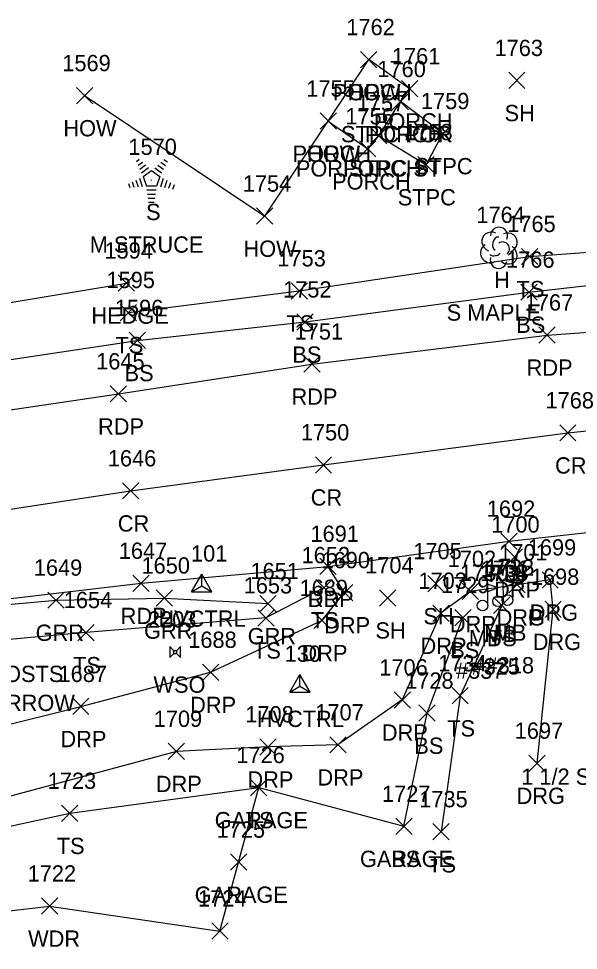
# Model space of a CAD drawing. Extents: x 1761340 to 1763889, y 696770 to 706023.
# Drawn here: x 1761848.8 to 1761917.6, y 700803.7 to 700918.1 of the extents above; entities that cross this region are included whole.
import ezdxf

# ---------------------------------------------------------------- set-up
doc = ezdxf.new("R2010")
doc.units = 0
for name, color, linetype in [('C_A', 7, 'Continuous'), ('C_I', 7, 'Continuous'), ('CPSM', 7, 'Continuous'), ('L_A', 7, 'Continuous'), ('L_C', 7, 'Continuous'), ('L_I', 7, 'Continuous'), ('L_TIC', 7, 'Continuous'), ('LAHR', 7, 'Continuous'), ('LAWA', 7, 'Continuous'), ('LBC', 7, 'Continuous'), ('LBF', 7, 'Continuous'), ('LELB', 7, 'Continuous'), ('LMB', 7, 'Continuous'), ('LTC', 7, 'Continuous'), ('LTD', 7, 'Continuous'), ('P_A', 7, 'Continuous'), ('P_I', 7, 'Continuous'), ('P_TIC', 7, 'Continuous'), ('PET', 7, 'Continuous'), ('PRC', 7, 'Continuous'), ('R_A', 7, 'Continuous'), ('R_C', 7, 'Continuous'), ('R_I', 7, 'Continuous'), ('R_TIC', 7, 'Continuous'), ('RDG', 7, 'Continuous'), ('RDP', 7, 'Continuous'), ('RGR', 7, 'Continuous'), ('S_C', 7, 'Continuous'), ('U_A', 7, 'Continuous'), ('U_I', 7, 'Continuous'), ('UWV', 7, 'Continuous')]:
    doc.layers.add(name, color=color, linetype=linetype)

msp = doc.modelspace()

# ---------------------------------------------------------------- linework, layer by layer
at = {"layer": 'CPSM'}
for p, q in [((1761870.08, 700847.74), (1761871.33, 700849.9)), ((1761872.58, 700847.74), (1761871.33, 700849.9)), ((1761871.33, 700848.46), (1761871.33, 700849.9)), ((1761870.08, 700847.74), (1761871.33, 700848.46)), ((1761871.33, 700848.46), (1761871.33, 700848.46)), ((1761871.33, 700848.46), (1761872.58, 700847.74)), ((1761870.08, 700847.74), (1761872.58, 700847.74)), ((1761882.15, 700835.43), (1761883.4, 700837.59)), ((1761884.65, 700835.43), (1761883.4, 700837.59)), ((1761883.4, 700836.15), (1761883.4, 700837.59)), ((1761882.15, 700835.43), (1761883.4, 700836.15)), ((1761882.15, 700835.43), (1761884.65, 700835.43)), ((1761883.4, 700836.15), (1761883.4, 700836.15)), ((1761883.4, 700836.15), (1761884.65, 700835.43))]:
    msp.add_line(p, q, dxfattribs=at)
at = {"layer": 'L_TIC'}
for points in [[(1761890.84, 700912.08), (1761892.84, 700914.08)], [(1761892.84, 700912.08), (1761890.84, 700914.08)], [(1761890.84, 700912.08), (1761892.84, 700914.08)], [(1761892.84, 700912.08), (1761890.84, 700914.08)], [(1761909.04, 700909.52), (1761911.04, 700911.52)], [(1761911.04, 700909.52), (1761909.04, 700911.52)], [(1761855.95, 700907.66), (1761857.95, 700909.66)], [(1761857.95, 700907.66), (1761855.95, 700909.66)], [(1761895.86, 700908.5), (1761897.86, 700910.5)], [(1761897.86, 700908.5), (1761895.86, 700910.5)], [(1761894.74, 700906.93), (1761896.74, 700908.93)], [(1761896.74, 700906.93), (1761894.74, 700908.93)], [(1761894.74, 700906.93), (1761896.74, 700908.93)], [(1761896.74, 700906.93), (1761894.74, 700908.93)], [(1761885.87, 700904.53), (1761887.87, 700906.53)], [(1761887.87, 700904.53), (1761885.87, 700906.53)], [(1761885.87, 700904.53), (1761887.87, 700906.53)], [(1761887.87, 700904.53), (1761885.87, 700906.53)], [(1761899.96, 700903), (1761901.96, 700905)], [(1761901.96, 700903), (1761899.96, 700905)], [(1761892.07, 700902.73), (1761894.07, 700904.73)], [(1761894.07, 700902.73), (1761892.07, 700904.73)], [(1761892.07, 700902.73), (1761894.07, 700904.73)], [(1761894.07, 700902.73), (1761892.07, 700904.73)], [(1761890.73, 700901.13), (1761892.73, 700903.13)], [(1761892.73, 700901.13), (1761890.73, 700903.13)], [(1761897.89, 700899.18), (1761899.89, 700901.18)], [(1761899.89, 700899.18), (1761897.89, 700901.18)], [(1761878.08, 700892.87), (1761880.08, 700894.87)], [(1761880.08, 700892.87), (1761878.08, 700894.87)], [(1761910.6, 700887.91), (1761912.6, 700889.91)], [(1761912.6, 700887.91), (1761910.6, 700889.91)], [(1761861.08, 700884.65), (1761863.08, 700886.65)], [(1761863.08, 700884.65), (1761861.08, 700886.65)], [(1761882.32, 700883.69), (1761884.32, 700885.69)], [(1761884.32, 700883.69), (1761882.32, 700885.69)], [(1761910.52, 700883.53), (1761912.52, 700885.53)], [(1761912.52, 700883.53), (1761910.52, 700885.53)], [(1761861.33, 700881.03), (1761863.33, 700883.03)], [(1761863.33, 700881.03), (1761861.33, 700883.03)], [(1761883.03, 700879.87), (1761885.03, 700881.87)], [(1761885.03, 700879.87), (1761883.03, 700881.87)], [(1761862.42, 700877.6), (1761864.42, 700879.6)], [(1761864.42, 700877.6), (1761862.42, 700879.6)], [(1761885.34, 700847.25), (1761887.34, 700849.25)], [(1761887.34, 700847.25), (1761885.34, 700849.25)], [(1761899.09, 700847.75), (1761901.09, 700849.75)], [(1761901.09, 700847.75), (1761899.09, 700849.75)], [(1761893.18, 700846), (1761895.18, 700848)], [(1761895.18, 700846), (1761893.18, 700848)], [(1761907.19, 700845.07), (1761909.19, 700847.07)], [(1761909.19, 700845.07), (1761907.19, 700847.07)], [(1761878.23, 700843.54), (1761880.23, 700845.54)], [(1761880.23, 700843.54), (1761878.23, 700845.54)], [(1761902.42, 700843.58), (1761904.42, 700845.58)], [(1761904.42, 700843.58), (1761902.42, 700845.58)], [(1761856.13, 700841.74), (1761858.13, 700843.74)], [(1761858.13, 700841.74), (1761856.13, 700843.74)], [(1761902.08, 700833.98), (1761904.08, 700835.98)], [(1761904.08, 700833.98), (1761902.08, 700835.98)], [(1761898.01, 700831.85), (1761900.01, 700833.85)], [(1761900.01, 700831.85), (1761898.01, 700833.85)], [(1761877.34, 700822.71), (1761879.34, 700824.71)], [(1761879.34, 700822.71), (1761877.34, 700824.71)], [(1761877.34, 700822.71), (1761879.34, 700824.71)], [(1761879.34, 700822.71), (1761877.34, 700824.71)], [(1761854.12, 700819.55), (1761856.12, 700821.55)], [(1761856.12, 700819.55), (1761854.12, 700821.55)], [(1761895.17, 700817.96), (1761897.17, 700819.96)], [(1761897.17, 700817.96), (1761895.17, 700819.96)], [(1761895.17, 700817.96), (1761897.17, 700819.96)], [(1761897.17, 700817.96), (1761895.17, 700819.96)], [(1761899.74, 700817.29), (1761901.74, 700819.29)], [(1761901.74, 700817.29), (1761899.74, 700819.29)], [(1761874.87, 700813.56), (1761876.87, 700815.56)], [(1761876.87, 700813.56), (1761874.87, 700815.56)], [(1761851.65, 700808.17), (1761853.65, 700810.17)], [(1761853.65, 700808.17), (1761851.65, 700810.17)], [(1761872.57, 700805.1), (1761874.57, 700807.1)], [(1761874.57, 700805.1), (1761872.57, 700807.1)], [(1761872.57, 700805.1), (1761874.57, 700807.1)], [(1761874.57, 700805.1), (1761872.57, 700807.1)]]:
    msp.add_lwpolyline(points, dxfattribs=at)
at = {"layer": 'LAHR'}
msp.add_lwpolyline([(1761783.53, 700873.77), (1761811.68, 700880.78), (1761831.53, 700880.58), (1761862.08, 700885.65)], dxfattribs=at)
at = {"layer": 'LAWA'}
msp.add_lwpolyline([(1761809.72, 700797.14), (1761828.97, 700806.42), (1761852.65, 700809.17), (1761873.57, 700806.1)], dxfattribs=at)
at = {"layer": 'LBC'}
for points in [[(1761856.95, 700908.66), (1761879.08, 700893.87), (1761886.87, 700905.53), (1761891.84, 700913.08)], [(1761873.57, 700806.1), (1761875.87, 700814.56), (1761878.34, 700823.71), (1761896.17, 700818.96)]]:
    msp.add_lwpolyline(points, dxfattribs=at)
at = {"layer": 'LBF'}
for points in [[(1761886.87, 700905.53), (1761891.73, 700902.13), (1761893.07, 700903.73), (1761895.74, 700907.93), (1761896.86, 700909.5), (1761891.84, 700913.08)], [(1761893.07, 700903.73), (1761898.89, 700900.18), (1761900.96, 700904), (1761895.74, 700907.93)]]:
    msp.add_lwpolyline(points, dxfattribs=at)
at = {"layer": 'LELB'}
for points in [[(1761723.72, 700872.01), (1761760.57, 700872.12), (1761783.53, 700873.77), (1761799.17, 700869.89), (1761806.34, 700870.91), (1761834.79, 700874.3), (1761863.42, 700878.6), (1761884.03, 700880.87), (1761911.52, 700884.53), (1761932.35, 700886.9), (1761937.16, 700891.64), (1761941.25, 700901.22)], [(1761862.33, 700882.03), (1761883.32, 700884.69), (1761911.6, 700888.91), (1761929.47, 700890.2)], [(1761886.34, 700848.25), (1761879.23, 700844.54), (1761857.13, 700842.74), (1761842.27, 700841.38), (1761813.56, 700834.68), (1761793.54, 700831.19), (1761773.73, 700826.67), (1761754.24, 700823.85), (1761739.4, 700821.55)], [(1761908.19, 700846.07), (1761903.08, 700834.98), (1761900.74, 700818.29)], [(1761896.17, 700818.96), (1761899.01, 700832.85), (1761903.42, 700844.58)], [(1761805.48, 700793.43), (1761803.94, 700799.51), (1761808.7, 700806.69), (1761825.93, 700814.22), (1761855.12, 700820.55), (1761878.34, 700823.71)]]:
    msp.add_lwpolyline(points, dxfattribs=at)
at = {"layer": 'LMB'}
for p, q in [((1761908.38, 700849.18), (1761909.67, 700848.79)), ((1761908.39, 700846.58), (1761908.38, 700849.18)), ((1761909.54, 700849.33), (1761910.83, 700848.95)), ((1761909.54, 700846.74), (1761909.54, 700849.33)), ((1761909.54, 700848.43), (1761910.83, 700848.94)), ((1761906.48, 700848.67), (1761907.77, 700848.29)), ((1761906.49, 700846.08), (1761906.49, 700848.67)), ((1761906.49, 700847.77), (1761907.77, 700848.28)), ((1761908.38, 700848.28), (1761909.67, 700848.79)), ((1761908.89, 700846.73), (1761908.89, 700846.73)), ((1761905.83, 700846.07), (1761905.83, 700846.07)), ((1761907.73, 700846.58), (1761907.73, 700846.58))]:
    msp.add_line(p, q, dxfattribs=at)
for centre in [(1761905.83, 700846.07), (1761907.73, 700846.58), (1761908.89, 700846.73)]:
    msp.add_circle(centre, 0.656, dxfattribs=at)
at = {"layer": 'LTC'}
for p, q in [((1761863.31, 700900.58), (1761863.66, 700900.84)), ((1761863.52, 700900.12), (1761864.05, 700900.5)), ((1761866.33, 700900.48), (1761866.88, 700900.08)), ((1761866.7, 700900.82), (1761867.12, 700900.52)), ((1761863.73, 700899.65), (1761864.43, 700900.16)), ((1761863.94, 700899.19), (1761864.81, 700899.82)), ((1761864.16, 700898.73), (1761865.17, 700899.47)), ((1761865.17, 700899.47), (1761866.17, 700898.74)), ((1761865.59, 700899.78), (1761866.4, 700899.19)), ((1761865.96, 700900.13), (1761866.64, 700899.63)), ((1761863.25, 700898.3), (1761863.52, 700897.46)), ((1761863.71, 700898.51), (1761864.04, 700897.49)), ((1761864.16, 700898.73), (1761864.55, 700897.54)), ((1761866.17, 700898.74), (1761865.78, 700897.54)), ((1761866.61, 700898.47), (1761866.27, 700897.43)), ((1761867.05, 700898.22), (1761866.76, 700897.34)), ((1761862.34, 700897.86), (1761862.49, 700897.39)), ((1761862.79, 700898.08), (1761863.01, 700897.43)), ((1761865.78, 700897.54), (1761864.55, 700897.54)), ((1761865.74, 700897.04), (1761864.59, 700897.04)), ((1761867.5, 700897.97), (1761867.26, 700897.24)), ((1761867.94, 700897.72), (1761867.75, 700897.15)), ((1761865.66, 700896.54), (1761864.67, 700896.54)), ((1761865.57, 700896.04), (1761864.74, 700896.04)), ((1761865.49, 700895.54), (1761864.81, 700895.54))]:
    msp.add_line(p, q, dxfattribs=at)
at = {"layer": 'LTD'}
msp.add_line((1761907.81, 700890.03), (1761907.81, 700890.03), dxfattribs=at)
msp.add_line((1761907.81, 700890.03), (1761907.81, 700890.03), dxfattribs=at)
msp.add_arc((1761907.86, 700891.46), 1.05, 335.5272, 180.9563, dxfattribs=at)
for centre, major_axis, ratio, start_param, end_param in [((1761907.02, 700890.7), (1.21, -0.51), 0.895232, 1.570796, 4.712389), ((1761907.6, 700890.49), (-0.208, -0.792), 0.645439, 3.141593, 6.283185), ((1761908.85, 700890.61), (-1.14, -0.48), 0.949671, 1.570796, 4.712389), ((1761906.73, 700889.32), (0.58, -1.04), 0.959034, 3.141593, 6.283185), ((1761908.31, 700889.86), (-0.5, 0.667), 0.989748, 3.141593, 6.283185), ((1761908.81, 700889.2), (-1.09, 0.79), 0.841452, 1.570796, 4.712389), ((1761907.35, 700889.28), (-0.625, -0.083), 0.423636, 0, 3.141593), ((1761907.81, 700888.53), (0.26, 1.06), 0.942809, 1.570796, 4.712389)]:
    msp.add_ellipse(centre, major_axis=major_axis, ratio=ratio, start_param=start_param, end_param=end_param, dxfattribs=at)
at = {"layer": 'P_TIC'}
for points in [[(1761912.75, 700878.27), (1761914.75, 700880.27)], [(1761914.75, 700878.27), (1761912.75, 700880.27)], [(1761883.87, 700874.71), (1761885.87, 700876.71)], [(1761885.87, 700874.71), (1761883.87, 700876.71)], [(1761860.11, 700871.05), (1761862.11, 700873.05)], [(1761862.11, 700871.05), (1761860.11, 700873.05)], [(1761915.3, 700866.26), (1761917.3, 700868.26)], [(1761917.3, 700866.26), (1761915.3, 700868.26)], [(1761885.29, 700862.33), (1761887.29, 700864.33)], [(1761887.29, 700862.33), (1761885.29, 700864.33)], [(1761861.6, 700859.14), (1761863.6, 700861.14)], [(1761863.6, 700859.14), (1761861.6, 700861.14)], [(1761908.09, 700852.95), (1761910.09, 700854.95)], [(1761910.09, 700852.95), (1761908.09, 700854.95)], [(1761885.86, 700849.87), (1761887.86, 700851.87)], [(1761887.86, 700849.87), (1761885.86, 700851.87)], [(1761862.89, 700847.79), (1761864.89, 700849.79)], [(1761864.89, 700847.79), (1761862.89, 700849.79)]]:
    msp.add_lwpolyline(points, dxfattribs=at)
at = {"layer": 'PET'}
for points in [[(1761729.33, 700852.74), (1761740.9, 700853.18), (1761754.83, 700854.09), (1761780.55, 700856.28), (1761810.22, 700861.14), (1761821.19, 700866.01), (1761839.22, 700868.83), (1761861.11, 700872.05), (1761884.87, 700875.71), (1761913.75, 700879.27), (1761932.44, 700880.62), (1761962.06, 700884.59), (1761979.87, 700885.62), (1762011.62, 700885.45), (1762036.8, 700884.84)], [(1761729.33, 700852.74), (1761727.43, 700840.67), (1761725.47, 700828.38), (1761741.06, 700828.32), (1761766.65, 700830.86), (1761785.9, 700834.25), (1761810.86, 700839.79), (1761840.51, 700846.05), (1761863.89, 700848.79), (1761886.86, 700850.87), (1761909.09, 700853.95), (1761931.55, 700856.46), (1761961.83, 700859.61), (1761986.64, 700861.18), (1762018.61, 700861.2), (1762035.74, 700860.87)]]:
    msp.add_lwpolyline(points, dxfattribs=at)
at = {"layer": 'PRC'}
msp.add_lwpolyline([(1761727.43, 700840.67), (1761741.7, 700841.02), (1761763.59, 700842.8), (1761782.51, 700845.85), (1761809.01, 700850.75), (1761839.73, 700856.65), (1761862.6, 700860.14), (1761886.29, 700863.33), (1761916.3, 700867.26), (1761941.01, 700869.9), (1761962.56, 700871.62), (1761986.3, 700872.71), (1762008.01, 700873.29), (1762036.15, 700873.12)], dxfattribs=at)
at = {"layer": 'R_TIC'}
for points in [[(1761908.75, 700851.01), (1761910.75, 700853.01)], [(1761910.75, 700851.01), (1761908.75, 700853.01)], [(1761885.86, 700849.87), (1761887.86, 700851.87)], [(1761887.86, 700849.87), (1761885.86, 700851.87)], [(1761913.13, 700848.2), (1761915.13, 700850.2)], [(1761915.13, 700848.2), (1761913.13, 700850.2)], [(1761909.06, 700847.6), (1761911.06, 700849.6)], [(1761911.06, 700847.6), (1761909.06, 700849.6)], [(1761909.06, 700847.6), (1761911.06, 700849.6)], [(1761911.06, 700847.6), (1761909.06, 700849.6)], [(1761865.76, 700845.98), (1761867.76, 700847.98)], [(1761867.76, 700845.98), (1761865.76, 700847.98)], [(1761887.88, 700846.64), (1761889.88, 700848.64)], [(1761889.88, 700846.64), (1761887.88, 700848.64)], [(1761903.32, 700846.79), (1761905.32, 700848.79)], [(1761905.32, 700846.79), (1761903.32, 700848.79)], [(1761852.45, 700845.72), (1761854.45, 700847.72)], [(1761854.45, 700845.72), (1761852.45, 700847.72)], [(1761878.49, 700845.3), (1761880.49, 700847.3)], [(1761880.49, 700845.3), (1761878.49, 700847.3)], [(1761899.72, 700844.11), (1761901.72, 700846.11)], [(1761901.72, 700844.11), (1761899.72, 700846.11)], [(1761913.5, 700844.6), (1761915.5, 700846.6)], [(1761915.5, 700844.6), (1761913.5, 700846.6)], [(1761885.1, 700843.23), (1761887.1, 700845.23)], [(1761887.1, 700843.23), (1761885.1, 700845.23)], [(1761871.42, 700836.86), (1761873.42, 700838.86)], [(1761873.42, 700836.86), (1761871.42, 700838.86)], [(1761894.97, 700833.47), (1761896.97, 700835.47)], [(1761896.97, 700833.47), (1761894.97, 700835.47)], [(1761855.49, 700832.67), (1761857.49, 700834.67)], [(1761857.49, 700832.67), (1761855.49, 700834.67)], [(1761878.46, 700827.71), (1761880.46, 700829.71)], [(1761880.46, 700827.71), (1761878.46, 700829.71)], [(1761887.06, 700827.96), (1761889.06, 700829.96)], [(1761889.06, 700827.96), (1761887.06, 700829.96)], [(1761867.22, 700827.16), (1761869.22, 700829.16)], [(1761869.22, 700827.16), (1761867.22, 700829.16)], [(1761911.52, 700825.7), (1761913.52, 700827.7)], [(1761913.52, 700825.7), (1761911.52, 700827.7)]]:
    msp.add_lwpolyline(points, dxfattribs=at)
at = {"layer": 'RDG'}
msp.add_lwpolyline([(1761912.52, 700826.7), (1761914.5, 700845.6), (1761914.13, 700849.2), (1761910.06, 700848.6)], dxfattribs=at)
at = {"layer": 'RDP'}
for points in [[(1761909.75, 700852.01), (1761910.06, 700848.6), (1761904.32, 700847.79), (1761900.72, 700845.11), (1761895.97, 700834.47), (1761888.06, 700828.96), (1761879.46, 700828.71), (1761868.22, 700828.16), (1761843.53, 700821.53), (1761821.66, 700815.81), (1761806.46, 700808.73), (1761801.46, 700801.99), (1761799.74, 700797.31), (1761801.84, 700789.96)], [(1761792.74, 700783.52), (1761789.8, 700796.06), (1761790.69, 700806.51), (1761793.91, 700812.38), (1761809.19, 700820.93), (1761834.4, 700828.2), (1761856.49, 700833.67), (1761872.42, 700837.86), (1761886.1, 700844.23), (1761888.88, 700847.64), (1761886.86, 700850.87)]]:
    msp.add_lwpolyline(points, dxfattribs=at)
at = {"layer": 'RGR'}
msp.add_lwpolyline([(1761841.54, 700845.67), (1761853.45, 700846.72), (1761866.76, 700846.98), (1761879.49, 700846.3)], dxfattribs=at)
at = {"layer": 'UWV'}
for p, q in [((1761867.41, 700841.02), (1761867.96, 700840.47)), ((1761868.74, 700841.02), (1761868.19, 700840.47)), ((1761867.96, 700840.23), (1761867.41, 700839.69)), ((1761868.19, 700840.23), (1761868.74, 700839.69))]:
    msp.add_line(p, q, dxfattribs=at)
for points in [[(1761867.41, 700841.02), (1761867.41, 700839.69)], [(1761868.74, 700839.69), (1761868.74, 700841.02)]]:
    msp.add_lwpolyline(points, dxfattribs=at)
msp.add_lwpolyline([(1761868.31, 700840.35), (1761868.08, 700840.59), (1761867.84, 700840.35), (1761868.08, 700840.12)], close=True, dxfattribs=at)

# ---------------------------------------------------------------- texts
at = {"layer": 'C_A'}
for p in [(1761866.02, 700843.46), (1761878.1, 700831.15)]:
    msp.add_text('HVCTRL', height=2, dxfattribs=at).set_placement(p)
at = {"layer": 'C_I'}
for s, p in [('101', (1761870.02, 700851.46)), ('130', (1761881.52, 700839.15))]:
    msp.add_text(s, height=2, dxfattribs=at).set_placement(p)
at = {"layer": 'L_A'}
for s, p in [('PORCH', (1761887.46, 700908.08)), ('HOW', (1761889.23, 700908.08)), ('SH', (1761908.53, 700905.52)), ('PORCH', (1761892.48, 700904.5)), ('HOW', (1761854.34, 700903.66)), ('STPC POR', (1761888.44, 700902.93)), ('PORCH', (1761891.36, 700902.93)), ('PORCH', (1761882.49, 700900.53)), ('HOW', (1761884.26, 700900.53)), ('POR STPC ST', (1761882.9, 700898.73)), ('PORCH', (1761888.69, 700898.73)), ('STPC', (1761897.47, 700899)), ('PORCH', (1761887.35, 700897.13)), ('STPC', (1761895.41, 700895.18)), ('S', (1761864.5, 700893.38)), ('HOW', (1761876.46, 700888.87)), ('H', (1761907.24, 700885.03)), ('TS', (1761910.01, 700883.91)), ('HEDGE', (1761857.78, 700880.65)), ('TS', (1761881.73, 700879.69)), ('BS', (1761909.96, 700879.53)), ('TS', (1761860.74, 700877.03)), ('BS', (1761882.47, 700875.87)), ('BS', (1761861.86, 700873.6)), ('SH', (1761898.57, 700843.75)), ('TS', (1761884.75, 700843.25)), ('SH', (1761892.67, 700842)), ('MB', (1761906.04, 700841.58)), ('MB', (1761907.2, 700841.73)), ('MB', (1761904.14, 700841.07)), ('TS', (1761906.6, 700841.07)), ('TS', (1761877.64, 700839.54)), ('BS', (1761901.86, 700839.58)), ('TS', (1761855.54, 700837.74)), ('TS', (1761901.49, 700829.98)), ('BS', (1761897.45, 700827.85)), ('GARAGE', (1761872.93, 700818.71)), ('TS', (1761876.75, 700818.71)), ('TS', (1761853.53, 700815.55)), ('GARAGE', (1761890.77, 700813.96)), ('BS', (1761894.61, 700813.96)), ('TS', (1761899.15, 700813.29)), ('GARAGE', (1761870.47, 700809.56)), ('WDR', (1761850.01, 700804.17))]:
    msp.add_text(s, height=2, dxfattribs=at).set_placement(p)
at = {"layer": 'L_C'}
for s, p in [('M STRUCE', (1761857.58, 700889.38)), ('S MAPLE', (1761901.42, 700881.03)), ('#318', (1761906.2, 700837.73)), ('#337', (1761902.57, 700837.07)), ('#325', (1761904.47, 700837.58)), ('1 1/2 STORY WOOD FRAME#325', (1761910.58, 700824.05))]:
    msp.add_text(s, height=2, dxfattribs=at).set_placement(p)
at = {"layer": 'L_I'}
for s, p in [('1762', (1761889.1, 700916.08)), ('1762', (1761889.1, 700916.08)), ('1763', (1761907.3, 700913.52)), ('1761', (1761894.69, 700912.5)), ('1569', (1761854.21, 700911.66)), ('1760', (1761892.91, 700910.93)), ('1760', (1761892.91, 700910.93)), ('1755', (1761884.18, 700908.53)), ('1755', (1761884.18, 700908.53)), ('1757', (1761890.38, 700906.73)), ('1757', (1761890.38, 700906.73)), ('1759', (1761898.26, 700907)), ('1756', (1761888.98, 700905.13)), ('1758', (1761896.2, 700903.18)), ('1570', (1761862.33, 700901.38)), ('1754', (1761876.38, 700896.87)), ('1764', (1761905.07, 700893.03)), ('1765', (1761908.86, 700891.91)), ('1594', (1761859.39, 700888.65)), ('1753', (1761880.63, 700887.69)), ('1766', (1761908.72, 700887.53)), ('1595', (1761859.64, 700885.03)), ('1752', (1761881.33, 700883.87)), ('1596', (1761860.67, 700881.6)), ('1705', (1761897.32, 700851.75)), ('1652', (1761883.6, 700851.25)), ('1704', (1761891.41, 700850)), ('1731', (1761905.6, 700849.58)), ('1732', (1761906.2, 700849.73)), ('1730', (1761903.05, 700849.07)), ('1733', (1761905.5, 700849.07)), ('1653', (1761876.49, 700847.54)), ('1729', (1761900.72, 700847.58)), ('1654', (1761854.39, 700845.74)), ('1734', (1761900.38, 700837.98)), ('1728', (1761896.32, 700835.85)), ('1726', (1761875.59, 700826.71)), ('1726', (1761875.59, 700826.71)), ('1723', (1761852.42, 700823.55)), ('1727', (1761893.48, 700821.96)), ('1727', (1761893.48, 700821.96)), ('1735', (1761898.05, 700821.29)), ('1725', (1761873.17, 700817.56)), ('1722', (1761849.95, 700812.17)), ('1724', (1761870.88, 700809.1)), ('1724', (1761870.88, 700809.1))]:
    msp.add_text(s, height=2, dxfattribs=at).set_placement(p)
at = {"layer": 'LTC'}
msp.add_text('.', height=1.04, rotation=270, dxfattribs=at).set_placement((1761865.05, 700898.48))
at = {"layer": 'P_A'}
for s, p in [('RDP', (1761911.24, 700874.27)), ('RDP', (1761882.36, 700870.71)), ('RDP', (1761858.6, 700867.05)), ('CR', (1761914.73, 700862.26)), ('CR', (1761884.72, 700858.33)), ('CR', (1761861.03, 700855.14)), ('RDP', (1761906.57, 700848.95)), ('RDP', (1761884.35, 700845.87)), ('RDP', (1761861.38, 700843.79))]:
    msp.add_text(s, height=2, dxfattribs=at).set_placement(p)
at = {"layer": 'P_I'}
for s, p in [('1767', (1761911.01, 700882.27)), ('1751', (1761882.75, 700878.71)), ('1645', (1761858.37, 700875.05)), ('1768', (1761913.56, 700870.26)), ('1750', (1761883.51, 700866.33)), ('1646', (1761859.8, 700863.14)), ('1692', (1761906.35, 700856.95)), ('1691', (1761884.69, 700853.87)), ('1647', (1761861.15, 700851.79))]:
    msp.add_text(s, height=2, dxfattribs=at).set_placement(p)
at = {"layer": 'R_A'}
for s, p in [('DRP', (1761907.24, 700847.01)), ('DRP', (1761884.35, 700845.87)), ('DRG', (1761907.55, 700843.6)), ('DRP', (1761907.55, 700843.6)), ('DRG', (1761911.62, 700844.2)), ('DRP', (1761886.37, 700842.64)), ('DRP', (1761901.81, 700842.79)), ('GRR', (1761850.94, 700841.72)), ('GRR', (1761864.25, 700841.98)), ('GRR', (1761876.98, 700841.3)), ('DRP', (1761898.21, 700840.11)), ('DRG', (1761911.99, 700840.6)), ('DRP', (1761883.59, 700839.23)), ('DRP', (1761869.91, 700832.86)), ('DRP', (1761853.98, 700828.67)), ('DRP', (1761893.46, 700829.47)), ('DRP', (1761865.7, 700823.16)), ('DRP', (1761876.95, 700823.71)), ('DRP', (1761885.55, 700823.96)), ('DRG', (1761910.01, 700821.7))]:
    msp.add_text(s, height=2, dxfattribs=at).set_placement(p)
at = {"layer": 'R_C'}
msp.add_text('SGR W/ WOOD POSTS', height=2, dxfattribs=at).set_placement((1761825.37, 700836.67))
at = {"layer": 'R_I'}
for s, p in [('1700', (1761906.89, 700855.01)), ('1691', (1761884.69, 700853.87)), ('1701', (1761907.86, 700851.6)), ('1701', (1761907.86, 700851.6)), ('1699', (1761911.38, 700852.2)), ('1690', (1761886.05, 700850.64)), ('1702', (1761901.55, 700850.79)), ('1649', (1761850.71, 700849.72)), ('1650', (1761863.94, 700849.98)), ('1651', (1761877.32, 700849.3)), ('1703', (1761897.95, 700848.11)), ('1698', (1761911.76, 700848.6)), ('1689', (1761883.35, 700847.23)), ('1688', (1761869.68, 700840.86)), ('1687', (1761853.75, 700836.67)), ('1706', (1761893.15, 700837.47)), ('1709', (1761865.44, 700831.16)), ('1708', (1761876.69, 700831.71)), ('1707', (1761885.29, 700831.96)), ('1697', (1761909.78, 700829.7))]:
    msp.add_text(s, height=2, dxfattribs=at).set_placement(p)
at = {"layer": 'S_C'}
msp.add_text('CURVE RT ARROW', height=2, dxfattribs=at).set_placement((1761831.09, 700833.11))
at = {"layer": 'U_A'}
msp.add_text('WSO', height=2, dxfattribs=at).set_placement((1761865.41, 700835.35))
at = {"layer": 'U_I'}
msp.add_text('2203', height=2, dxfattribs=at).set_placement((1761864.74, 700843.35))

doc.saveas('drawing.dxf')
